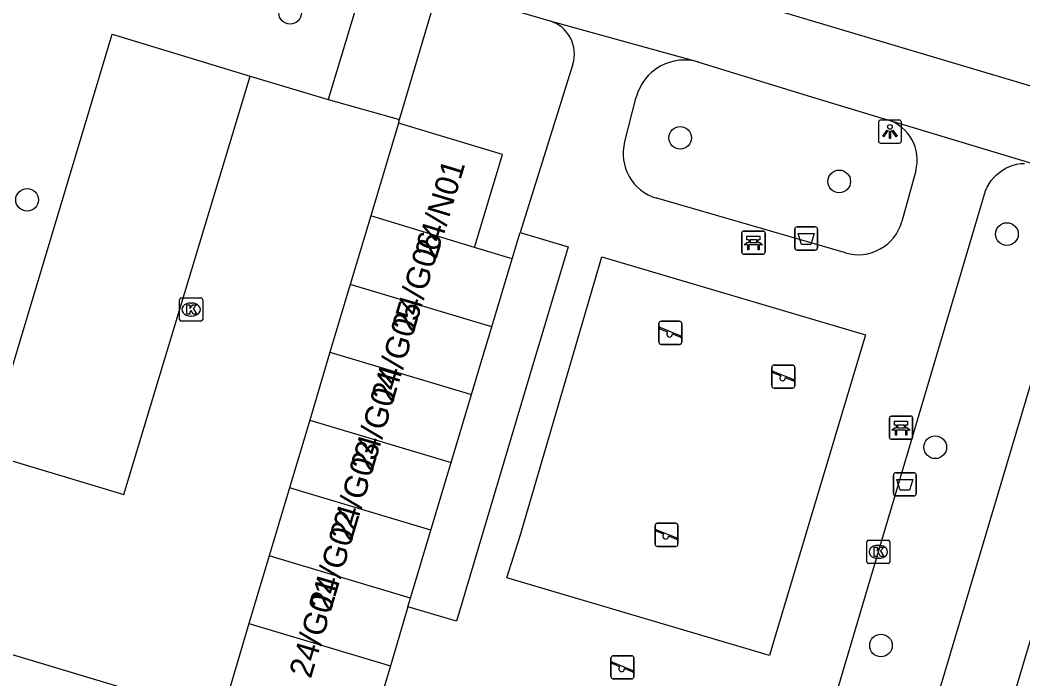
# Model space of a CAD drawing. Extents: x 162186 to 163152, y 385513 to 386513.
# Drawn here: x 162623.88 to 162667.22, y 386152.72 to 386181.19 of the extents above; entities that cross this region are included whole.
import ezdxf

# ---------------------------------------------------------------- set-up
doc = ezdxf.new("R2010")
doc.units = 0
for name, color, linetype in [('IMGEO_Afvalbak', 7, 'Continuous'), ('IMGEO_Bank', 7, 'Continuous'), ('IMGEO_Boom', 7, 'Continuous'), ('IMGEO_Groenvoorziening', 7, 'Continuous'), ('IMGEO_Kolk', 7, 'Continuous'), ('IMGEO_Lichtpunt', 7, 'Continuous'), ('IMGEO_Pand', 7, 'Continuous'), ('IMGEO_Pand_nummerreeks', 7, 'Continuous'), ('IMGEO_Parkeervlak_open', 7, 'Continuous'), ('IMGEO_Rijbaan_lokaal_open', 7, 'Continuous'), ('IMGEO_Speelvoorziening', 7, 'Continuous'), ('IMGEO_Voetpad_open', 7, 'Continuous')]:
    doc.layers.add(name, color=color, linetype=linetype)

msp = doc.modelspace()

# ---------------------------------------------------------------- linework, layer by layer
at = {"layer": 'IMGEO_Afvalbak'}
for p, q in [((162657.358, 386171.353), (162657.358, 386172.153)), ((162657.358, 386172.153), (162657.358, 386171.353)), ((162657.458, 386172.253), (162658.248, 386172.253)), ((162658.248, 386172.253), (162657.458, 386172.253)), ((162658.348, 386172.153), (162658.348, 386171.353)), ((162658.348, 386171.353), (162658.348, 386172.153)), ((162658.248, 386171.253), (162657.458, 386171.253)), ((162657.458, 386171.253), (162658.248, 386171.253)), ((162661.622, 386160.73), (162661.622, 386161.53)), ((162661.622, 386161.53), (162661.622, 386160.73)), ((162661.722, 386161.63), (162662.512, 386161.63)), ((162662.512, 386161.63), (162661.722, 386161.63)), ((162662.612, 386161.53), (162662.612, 386160.73)), ((162662.612, 386160.73), (162662.612, 386161.53)), ((162662.512, 386160.63), (162661.722, 386160.63)), ((162661.722, 386160.63), (162662.512, 386160.63))]:
    msp.add_line(p, q, dxfattribs=at)
for points in [[(162657.501, 386171.967), (162658.205, 386171.967), (162658.056, 386171.497), (162657.65, 386171.497), (162657.501, 386171.967)], [(162661.765, 386161.344), (162662.469, 386161.344), (162662.32, 386160.874), (162661.914, 386160.874), (162661.765, 386161.344)]]:
    msp.add_lwpolyline(points, dxfattribs=at)
for centre, start, end in [((162657.458, 386172.153), 90, 180), ((162657.458, 386172.153), 90, 180), ((162658.248, 386172.153), 0, 90), ((162658.248, 386172.153), 360, 90), ((162657.458, 386171.353), 180, 270), ((162657.458, 386171.353), 180, 270), ((162658.248, 386171.353), 270, 0), ((162658.248, 386171.353), 270, 0), ((162661.722, 386161.53), 90, 180), ((162661.722, 386161.53), 90, 180), ((162662.512, 386161.53), 0, 90), ((162662.512, 386161.53), 360, 90), ((162661.722, 386160.73), 180, 270), ((162661.722, 386160.73), 180, 270), ((162662.512, 386160.73), 270, 0), ((162662.512, 386160.73), 270, 0)]:
    msp.add_arc(centre, 0.1, start, end, dxfattribs=at)
at = {"layer": 'IMGEO_Bank'}
for p, q in [((162655.076, 386171.149), (162655.076, 386171.99)), ((162655.076, 386171.99), (162655.076, 386171.149)), ((162655.151, 386172.074), (162655.992, 386172.074)), ((162655.992, 386172.074), (162655.151, 386172.074)), ((162656.076, 386171.999), (162656.076, 386171.158)), ((162656.076, 386171.158), (162656.076, 386171.999)), ((162655.773, 386171.472), (162655.38, 386171.472)), ((162655.385, 386171.58), (162655.385, 386171.686)), ((162655.429, 386171.686), (162655.429, 386171.58)), ((162655.717, 386171.692), (162655.435, 386171.692)), ((162655.435, 386171.574), (162655.717, 386171.574)), ((162655.723, 386171.58), (162655.723, 386171.686)), ((162655.767, 386171.686), (162655.767, 386171.58)), ((162656.001, 386171.074), (162655.16, 386171.074)), ((162655.16, 386171.074), (162656.001, 386171.074)), ((162661.529, 386164.074), (162662.37, 386164.074)), ((162662.37, 386164.074), (162661.529, 386164.074)), ((162661.454, 386163.149), (162661.454, 386163.99)), ((162661.454, 386163.99), (162661.454, 386163.149)), ((162661.763, 386163.58), (162661.763, 386163.686)), ((162661.807, 386163.686), (162661.807, 386163.58)), ((162662.095, 386163.692), (162661.813, 386163.692)), ((162662.101, 386163.58), (162662.101, 386163.686)), ((162662.145, 386163.686), (162662.145, 386163.58)), ((162662.454, 386163.999), (162662.454, 386163.158)), ((162662.454, 386163.158), (162662.454, 386163.999)), ((162662.151, 386163.472), (162661.758, 386163.472)), ((162661.813, 386163.574), (162662.095, 386163.574)), ((162662.379, 386163.074), (162661.538, 386163.074)), ((162661.538, 386163.074), (162662.379, 386163.074))]:
    msp.add_line(p, q, dxfattribs=at)
for points in [[(162655.379, 386171.692), (162655.293, 386171.692), (162655.293, 386171.853), (162655.856, 386171.853), (162655.856, 386171.692), (162655.773, 386171.692)], [(162655.323, 386171.472), (162655.181, 386171.472), (162655.293, 386171.574), (162655.379, 386171.574)], [(162655.373, 386171.465), (162655.373, 386171.258), (162655.33, 386171.258), (162655.33, 386171.465)], [(162655.773, 386171.574), (162655.856, 386171.574), (162655.968, 386171.472), (162655.829, 386171.472)], [(162655.823, 386171.465), (162655.823, 386171.258), (162655.779, 386171.258), (162655.779, 386171.465)], [(162661.757, 386163.692), (162661.671, 386163.692), (162661.671, 386163.853), (162662.234, 386163.853), (162662.234, 386163.692), (162662.151, 386163.692)], [(162661.701, 386163.472), (162661.559, 386163.472), (162661.671, 386163.574), (162661.757, 386163.574)], [(162661.751, 386163.465), (162661.751, 386163.258), (162661.708, 386163.258), (162661.708, 386163.465)], [(162662.151, 386163.574), (162662.234, 386163.574), (162662.346, 386163.472), (162662.207, 386163.472)], [(162662.201, 386163.465), (162662.201, 386163.258), (162662.157, 386163.258), (162662.157, 386163.465)]]:
    msp.add_lwpolyline(points, dxfattribs=at)
for centre, radius, start, end in [((162655.154, 386171.996), 0.0779, 92.4484, 184.2845), ((162655.154, 386171.996), 0.0779, 92.4484, 184.2845), ((162655.998, 386171.996), 0.0779, 2.4484, 94.2845), ((162655.998, 386171.996), 0.0779, 2.4484, 94.2845), ((162655.323, 386171.465), 0.00671, 2.8957, 87.1043), ((162655.38, 386171.465), 0.00671, 92.8957, 177.1043), ((162655.378, 386171.685), 0.00671, 2.8957, 87.1043), ((162655.378, 386171.581), 0.00671, 272.8957, 357.1043), ((162655.435, 386171.685), 0.00671, 92.8957, 177.1043), ((162655.435, 386171.581), 0.00671, 182.8957, 267.1043), ((162655.717, 386171.685), 0.00671, 2.8957, 87.1043), ((162655.717, 386171.581), 0.00671, 272.8957, 357.1043), ((162655.774, 386171.685), 0.00671, 92.8957, 177.1043), ((162655.774, 386171.581), 0.00671, 182.8957, 267.1043), ((162655.772, 386171.465), 0.00671, 2.8957, 87.1043), ((162655.829, 386171.465), 0.00671, 92.8957, 177.1043), ((162655.154, 386171.152), 0.0779, 182.4484, 274.2845), ((162655.154, 386171.152), 0.0779, 182.4484, 274.2845), ((162655.998, 386171.152), 0.0779, 272.4484, 4.2845), ((162655.998, 386171.152), 0.0779, 272.4484, 4.2845), ((162661.532, 386163.996), 0.0779, 92.4484, 184.2845), ((162661.532, 386163.996), 0.0779, 92.4484, 184.2845), ((162662.376, 386163.996), 0.0779, 2.4484, 94.2845), ((162662.376, 386163.996), 0.0779, 2.4484, 94.2845), ((162661.756, 386163.685), 0.00671, 2.8957, 87.1043), ((162661.813, 386163.685), 0.00671, 92.8957, 177.1043), ((162662.095, 386163.685), 0.00671, 2.8957, 87.1043), ((162662.152, 386163.685), 0.00671, 92.8957, 177.1043), ((162661.701, 386163.465), 0.00671, 2.8957, 87.1043), ((162661.758, 386163.465), 0.00671, 92.8957, 177.1043), ((162661.756, 386163.581), 0.00671, 272.8957, 357.1043), ((162661.813, 386163.581), 0.00671, 182.8957, 267.1043), ((162662.095, 386163.581), 0.00671, 272.8957, 357.1043), ((162662.152, 386163.581), 0.00671, 182.8957, 267.1043), ((162662.15, 386163.465), 0.00671, 2.8957, 87.1043), ((162662.207, 386163.465), 0.00671, 92.8957, 177.1043), ((162661.532, 386163.152), 0.0779, 182.4484, 274.2845), ((162661.532, 386163.152), 0.0779, 182.4484, 274.2845), ((162662.376, 386163.152), 0.0779, 272.4484, 4.2845), ((162662.376, 386163.152), 0.0779, 272.4484, 4.2845)]:
    msp.add_arc(centre, radius, start, end, dxfattribs=at)
at = {"layer": 'IMGEO_Boom'}
for centre in [(162635.553, 386181.509), (162652.406, 386176.105), (162659.283, 386174.22), (162624.188, 386173.425), (162666.529, 386171.944), (162663.432, 386162.73), (162661.087, 386154.162)]:
    msp.add_circle(centre, 0.489, dxfattribs=at)
at = {"layer": 'IMGEO_Groenvoorziening'}
msp.add_lwpolyline([(162645.144, 386170.871), (162645.385, 386171.642), (162645.498, 386172.005)], dxfattribs=at)
at = {"layer": 'IMGEO_Kolk'}
for p, q in [((162630.776, 386168.255), (162630.776, 386169.107)), ((162630.851, 386169.181), (162631.703, 386169.181)), ((162631.264, 386168.961), (162631.289, 386168.961)), ((162631.777, 386169.107), (162631.777, 386168.255)), ((162631.287, 386168.401), (162631.262, 386168.401)), ((162631.703, 386168.181), (162630.851, 386168.181)), ((162660.471, 386157.785), (162660.471, 386158.637)), ((162660.546, 386158.711), (162661.398, 386158.711)), ((162660.959, 386158.491), (162660.984, 386158.491)), ((162661.472, 386158.637), (162661.472, 386157.785)), ((162661.398, 386157.711), (162660.546, 386157.711)), ((162660.982, 386157.931), (162660.957, 386157.931))]:
    msp.add_line(p, q, dxfattribs=at)
for points in [[(162630.776, 386168.255), (162630.776, 386169.107)], [(162630.851, 386169.181), (162631.703, 386169.181)], [(162631.097, 386168.881), (162631.22, 386168.881), (162631.22, 386168.73), (162631.35, 386168.881), (162631.514, 386168.881), (162631.368, 386168.73), (162631.521, 386168.481), (162631.369, 386168.481), (162631.284, 386168.645), (162631.22, 386168.578), (162631.22, 386168.481), (162631.097, 386168.481), (162631.097, 386168.881)], [(162631.777, 386169.107), (162631.777, 386168.255)], [(162631.703, 386168.181), (162630.851, 386168.181)], [(162660.471, 386157.785), (162660.471, 386158.637)], [(162660.546, 386158.711), (162661.398, 386158.711)], [(162660.792, 386158.411), (162660.915, 386158.411), (162660.915, 386158.26), (162661.045, 386158.411), (162661.209, 386158.411), (162661.063, 386158.26), (162661.216, 386158.011), (162661.064, 386158.011), (162660.979, 386158.175), (162660.915, 386158.108), (162660.915, 386158.011), (162660.792, 386158.011), (162660.792, 386158.411)], [(162661.472, 386158.637), (162661.472, 386157.785)], [(162661.398, 386157.711), (162660.546, 386157.711)]]:
    msp.add_lwpolyline(points, dxfattribs=at)
for centre, start, end in [((162630.853, 386169.105), 91.552, 178.448), ((162630.853, 386169.105), 91.552, 178.448), ((162631.701, 386169.105), 1.552, 88.448), ((162631.701, 386169.105), 1.552, 88.448), ((162630.853, 386168.257), 181.552, 268.448), ((162630.853, 386168.257), 181.552, 268.448), ((162631.701, 386168.257), 271.552, 358.448), ((162631.701, 386168.257), 271.552, 358.448), ((162660.548, 386158.635), 91.552, 178.448), ((162660.548, 386158.635), 91.552, 178.448), ((162661.396, 386158.635), 1.552, 88.448), ((162661.396, 386158.635), 1.552, 88.448), ((162660.548, 386157.787), 181.552, 268.448), ((162660.548, 386157.787), 181.552, 268.448), ((162661.396, 386157.787), 271.552, 358.448), ((162661.396, 386157.787), 271.552, 358.448)]:
    msp.add_arc(centre, 0.0765, start, end, dxfattribs=at)
for centre, major_axis, ratio, start_param, end_param in [((162631.263, 386168.681), (-0.387, 0.002), 0.722429, 4.712389, 7.853982), ((162631.288, 386168.681), (-0.39, 0.002), 0.717154, 1.570796, 4.712389), ((162660.958, 386158.211), (-0.387, 0.002), 0.722429, 4.712389, 7.853982), ((162660.983, 386158.211), (-0.39, 0.002), 0.717154, 1.570796, 4.712389)]:
    msp.add_ellipse(centre, major_axis=major_axis, ratio=ratio, start_param=start_param, end_param=end_param, dxfattribs=at)
at = {"layer": 'IMGEO_Lichtpunt'}
for p, q in [((162660.975, 386176.776), (162660.975, 386175.969)), ((162660.975, 386176.776), (162660.975, 386175.969)), ((162661.877, 386176.871), (162661.069, 386176.871)), ((162661.877, 386176.871), (162661.069, 386176.871)), ((162661.971, 386175.969), (162661.971, 386176.776)), ((162661.971, 386175.969), (162661.971, 386176.776)), ((162661.069, 386175.875), (162661.877, 386175.875)), ((162661.069, 386175.875), (162661.877, 386175.875))]:
    msp.add_line(p, q, dxfattribs=at)
for points in [[(162661.349, 386176.44), (162661.388, 386176.412), (162661.2, 386176.15), (162661.162, 386176.177), (162661.349, 386176.44)], [(162661.451, 386176.392), (162661.498, 386176.392), (162661.498, 386176.07), (162661.451, 386176.07), (162661.451, 386176.392)], [(162661.561, 386176.412), (162661.599, 386176.439), (162661.786, 386176.177), (162661.747, 386176.149), (162661.561, 386176.412)]]:
    msp.add_lwpolyline(points, dxfattribs=at)
msp.add_circle((162661.474, 386176.574), 0.0994, dxfattribs=at)
for centre, start, end in [((162661.069, 386176.776), 90, 180), ((162661.069, 386176.776), 90, 180), ((162661.877, 386176.776), 0, 90), ((162661.877, 386176.776), 0, 90), ((162661.069, 386175.969), 180, 270), ((162661.069, 386175.969), 180, 270), ((162661.877, 386175.969), 270, 0), ((162661.877, 386175.969), 270, 360)]:
    msp.add_arc(centre, 0.0946, start, end, dxfattribs=at)
at = {"layer": 'IMGEO_Pand'}
for points in [[(162640.234, 386176.73), (162639.038, 386172.73)], [(162643.52, 386171.356), (162644.725, 386175.388), (162640.234, 386176.73)], [(162639.038, 386172.73), (162638.153, 386169.768)], [(162643.52, 386171.356), (162639.038, 386172.73)], [(162645.144, 386170.871), (162643.52, 386171.356)], [(162644.268, 386167.94), (162645.144, 386170.871)], [(162638.153, 386169.768), (162637.276, 386166.837)], [(162644.268, 386167.94), (162638.153, 386169.768)], [(162643.391, 386165.009), (162643.838, 386166.503), (162644.268, 386167.94)], [(162637.276, 386166.837), (162636.4, 386163.905)], [(162637.276, 386166.837), (162643.391, 386165.009)], [(162642.515, 386162.078), (162643.391, 386165.009)], [(162636.4, 386163.905), (162635.524, 386160.974)], [(162636.4, 386163.905), (162642.515, 386162.078)], [(162641.639, 386159.146), (162642.515, 386162.078)], [(162635.524, 386160.974), (162634.648, 386158.043)], [(162641.639, 386159.146), (162635.524, 386160.974)], [(162640.763, 386156.215), (162641.639, 386159.146)], [(162634.648, 386158.043), (162633.772, 386155.112)], [(162640.763, 386156.215), (162634.648, 386158.043)], [(162640.647, 386155.828), (162639.887, 386153.284)], [(162640.647, 386155.828), (162640.763, 386156.215)], [(162633.772, 386155.112), (162639.887, 386153.284)]]:
    msp.add_lwpolyline(points, dxfattribs=at)
at = {"layer": 'IMGEO_Parkeervlak_open'}
msp.add_lwpolyline([(162622.424, 386162.478), (162627.867, 386180.578), (162633.835, 386178.773)], dxfattribs=at)
at = {"layer": 'IMGEO_Rijbaan_lokaal_open'}
for points in [[(162622.424, 386162.478), (162628.365, 386160.692), (162633.835, 386178.773)], [(162633.835, 386178.773), (162637.202, 386177.754)], [(162637.202, 386177.754), (162640.282, 386176.891)], [(162640.234, 386176.73), (162640.282, 386176.891)], [(162632.571, 386151.052), (162591.943, 386163.26)], [(162633.772, 386155.112), (162632.571, 386151.052)]]:
    msp.add_lwpolyline(points, dxfattribs=at)
at = {"layer": 'IMGEO_Speelvoorziening'}
for p, q in [((162651.488, 386167.276), (162651.488, 386168.076)), ((162651.488, 386168.076), (162651.488, 386167.276)), ((162651.588, 386168.176), (162652.378, 386168.176)), ((162652.378, 386168.176), (162651.588, 386168.176)), ((162652.478, 386168.076), (162652.478, 386167.276)), ((162652.478, 386167.276), (162652.478, 386168.076)), ((162651.871, 386167.704), (162651.532, 386167.841)), ((162651.557, 386167.901), (162652.433, 386167.548)), ((162652.409, 386167.488), (162652.069, 386167.625)), ((162652.378, 386167.176), (162651.588, 386167.176)), ((162651.588, 386167.176), (162652.378, 386167.176)), ((162656.469, 386166.284), (162657.259, 386166.284)), ((162657.259, 386166.284), (162656.469, 386166.284)), ((162656.369, 386165.384), (162656.369, 386166.184)), ((162656.369, 386166.184), (162656.369, 386165.384)), ((162656.752, 386165.812), (162656.413, 386165.949)), ((162656.438, 386166.009), (162657.314, 386165.656)), ((162657.359, 386166.184), (162657.359, 386165.384)), ((162657.359, 386165.384), (162657.359, 386166.184)), ((162657.29, 386165.596), (162656.95, 386165.733)), ((162657.259, 386165.284), (162656.469, 386165.284)), ((162656.469, 386165.284), (162657.259, 386165.284)), ((162651.322, 386158.544), (162651.322, 386159.344)), ((162651.322, 386159.344), (162651.322, 386158.544)), ((162651.422, 386159.444), (162652.212, 386159.444)), ((162652.212, 386159.444), (162651.422, 386159.444)), ((162652.312, 386159.344), (162652.312, 386158.544)), ((162652.312, 386158.544), (162652.312, 386159.344)), ((162651.705, 386158.972), (162651.366, 386159.109)), ((162651.391, 386159.169), (162652.267, 386158.816)), ((162652.243, 386158.756), (162651.903, 386158.893)), ((162652.212, 386158.444), (162651.422, 386158.444)), ((162651.422, 386158.444), (162652.212, 386158.444)), ((162649.52, 386153.718), (162650.31, 386153.718)), ((162650.31, 386153.718), (162649.52, 386153.718)), ((162649.42, 386152.818), (162649.42, 386153.618)), ((162649.42, 386153.618), (162649.42, 386152.818)), ((162649.803, 386153.246), (162649.464, 386153.383)), ((162649.489, 386153.443), (162650.365, 386153.09)), ((162650.41, 386153.618), (162650.41, 386152.818)), ((162650.41, 386152.818), (162650.41, 386153.618)), ((162650.341, 386153.03), (162650.001, 386153.167)), ((162650.31, 386152.718), (162649.52, 386152.718)), ((162649.52, 386152.718), (162650.31, 386152.718))]:
    msp.add_line(p, q, dxfattribs=at)
for centre, radius, start, end in [((162651.588, 386168.076), 0.1, 90, 180), ((162651.588, 386168.076), 0.1, 90, 180), ((162652.378, 386168.076), 0.1, 0, 90), ((162652.378, 386168.076), 0.1, 360, 90), ((162651.545, 386167.871), 0.0327, 68.078, 248.078), ((162651.95, 386167.614), 0.12, 130.9928, 5.1632), ((162652.421, 386167.518), 0.0327, 248.078, 68.078), ((162651.588, 386167.276), 0.1, 180, 270), ((162651.588, 386167.276), 0.1, 180, 270), ((162652.378, 386167.276), 0.1, 270, 0), ((162652.378, 386167.276), 0.1, 270, 0), ((162656.469, 386166.184), 0.1, 90, 180), ((162656.469, 386166.184), 0.1, 90, 180), ((162657.259, 386166.184), 0.1, 0, 90), ((162657.259, 386166.184), 0.1, 360, 90), ((162656.426, 386165.979), 0.0327, 68.078, 248.078), ((162656.831, 386165.722), 0.12, 130.9928, 5.1632), ((162656.469, 386165.384), 0.1, 180, 270), ((162656.469, 386165.384), 0.1, 180, 270), ((162657.259, 386165.384), 0.1, 270, 0), ((162657.259, 386165.384), 0.1, 270, 0), ((162657.302, 386165.626), 0.0327, 248.078, 68.078), ((162651.422, 386159.344), 0.1, 90, 180), ((162651.422, 386159.344), 0.1, 90, 180), ((162652.212, 386159.344), 0.1, 0, 90), ((162652.212, 386159.344), 0.1, 360, 90), ((162651.379, 386159.139), 0.0327, 68.078, 248.078), ((162651.784, 386158.882), 0.12, 130.9928, 5.1632), ((162651.422, 386158.544), 0.1, 180, 270), ((162651.422, 386158.544), 0.1, 180, 270), ((162652.212, 386158.544), 0.1, 270, 0), ((162652.212, 386158.544), 0.1, 270, 0), ((162652.255, 386158.786), 0.0327, 248.078, 68.078), ((162649.52, 386153.618), 0.1, 90, 180), ((162649.52, 386153.618), 0.1, 90, 180), ((162650.31, 386153.618), 0.1, 0, 90), ((162650.31, 386153.618), 0.1, 360, 90), ((162649.477, 386153.413), 0.0327, 68.078, 248.078), ((162649.882, 386153.156), 0.12, 130.9928, 5.1632), ((162649.52, 386152.818), 0.1, 180, 270), ((162649.52, 386152.818), 0.1, 180, 270), ((162650.31, 386152.818), 0.1, 270, 0), ((162650.31, 386152.818), 0.1, 270, 0), ((162650.353, 386153.06), 0.0327, 248.078, 68.078)]:
    msp.add_arc(centre, radius, start, end, dxfattribs=at)
at = {"layer": 'IMGEO_Voetpad_open'}
for points in [[(162626.674, 386187.116), (162638.93, 386183.488), (162637.202, 386177.754)], [(162699.756, 386171.624), (162699.657, 386171.381), (162699.537, 386171.147), (162699.396, 386170.925), (162699.236, 386170.717), (162699.058, 386170.524), (162698.864, 386170.347), (162698.654, 386170.188), (162698.431, 386170.049), (162698.197, 386169.931), (162697.953, 386169.833), (162697.701, 386169.758), (162697.444, 386169.706), (162697.183, 386169.677), (162696.92, 386169.671), (162696.658, 386169.689), (162696.399, 386169.73), (162696.144, 386169.794), (162666.99, 386178.501), (162649.189, 386183.818), (162649.012, 386183.871)], [(162640.282, 386176.891), (162641.972, 386182.589), (162646.772, 386181.157)], [(162646.772, 386181.157), (162653.088, 386179.42), (162653.216, 386179.371)], [(162647.771, 386179.28), (162645.498, 386172.005)], [(162653.216, 386179.371), (162657.934, 386177.91), (162661.364, 386176.882)], [(162650.011, 386175.937), (162650.512, 386177.861)], [(162661.364, 386176.882), (162661.428, 386176.867), (162667.782, 386174.948)], [(162657.36, 386146.027), (162665.557, 386173.669), (162665.608, 386173.816), (162665.676, 386173.968), (162665.757, 386174.114), (162665.852, 386174.252), (162665.958, 386174.381), (162666.075, 386174.5), (162666.202, 386174.608), (162666.339, 386174.705), (162666.483, 386174.788), (162666.635, 386174.859), (162666.792, 386174.915), (162666.954, 386174.958), (162667.118, 386174.986), (162667.285, 386174.999)], [(162668.335, 386174.804), (162668.502, 386174.736), (162668.663, 386174.654), (162668.816, 386174.557), (162668.96, 386174.447), (162669.093, 386174.325), (162669.215, 386174.191), (162669.324, 386174.047), (162669.421, 386173.894), (162669.503, 386173.733), (162669.57, 386173.565), (162669.622, 386173.391), (162669.658, 386173.214), (162669.679, 386173.035), (162669.683, 386172.854), (162669.671, 386172.673), (162669.643, 386172.494), (162669.599, 386172.319), (162661.394, 386144.815), (162661.382, 386144.777), (162661.318, 386144.601)], [(162662.589, 386174.669), (162661.99, 386172.491)], [(162659.555, 386171.128), (162651.399, 386173.493)], [(162675.323, 386172.77), (162675.11, 386172.804), (162674.895, 386172.82), (162674.679, 386172.816), (162674.464, 386172.793), (162674.252, 386172.751), (162674.045, 386172.691), (162673.844, 386172.612), (162673.651, 386172.515), (162673.468, 386172.401), (162673.295, 386172.272), (162673.134, 386172.128), (162672.987, 386171.969), (162672.855, 386171.799), (162672.739, 386171.617), (162672.639, 386171.426), (162672.557, 386171.226), (162672.514, 386171.096), (162664.259, 386143.414)], [(162645.498, 386172.005), (162647.571, 386171.391), (162645.919, 386165.854), (162642.746, 386155.219), (162640.647, 386155.828)], [(162660.424, 386167.583), (162656.437, 386154.329), (162656.275, 386153.732), (162644.919, 386157.086), (162645.488, 386158.909), (162649.019, 386170.962), (162660.424, 386167.583)], [(162639.887, 386153.284), (162639.35, 386151.436)]]:
    msp.add_lwpolyline(points, dxfattribs=at)
for centre, radius, start, end in [((162646.345, 386179.725), 1.494, 342.6493, 73.3974), ((162652.589, 386177.318), 2.147, 73.0185, 165.3423), ((162660.843, 386175.148), 1.81, 344.6554, 73.2778), ((162651.959, 386175.427), 2.014, 165.3379, 253.8485), ((162660.101, 386173.009), 1.959, 253.8109, 344.6652)]:
    msp.add_arc(centre, radius, start, end, dxfattribs=at)

# ---------------------------------------------------------------- texts
at = {"layer": 'IMGEO_Pand_nummerreeks'}
for s, rotation, p in [('24/N01', 73.1625, (162641.879, 386170.831)), ('24/G06', 73.4282, (162640.896, 386167.648)), ('24/G05', 73.4282, (162640, 386164.638)), ('24/G04', 73.4282, (162639.104, 386161.627)), ('24/G03', 73.4282, (162638.208, 386158.617)), ('24/G02', 73.4282, (162637.311, 386155.6)), ('24/G01', 73.4282, (162636.448, 386152.702))]:
    msp.add_text(s, height=1, rotation=rotation, dxfattribs=at).set_placement(p)

doc.saveas('drawing.dxf')
